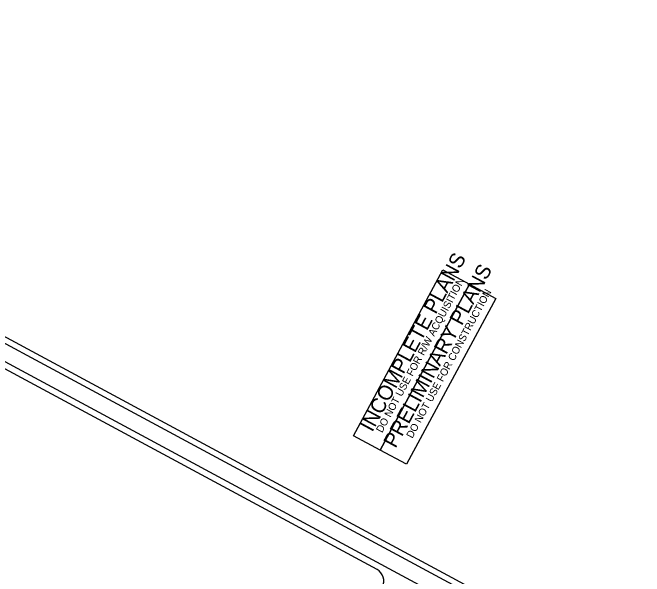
# Model space of a CAD drawing. Extents: x 1376167 to 1379209, y 761324 to 763997.
# Drawn here: x 1377441.6 to 1377934.3, y 763557.6 to 763997.5 of the extents above; entities that cross this region are included whole.
import ezdxf

# ---------------------------------------------------------------- set-up
doc = ezdxf.new("R2010")
doc.units = 0
for name, color, linetype in [('Sheet Plot Border Inside CELL', 7, 'Continuous'), ('Sheet Plot Border Outside CELL', 7, 'Continuous'), ('Sheet Sticker Incomplete CELL', 7, 'Continuous'), ('Sheet Sticker Preliminary CELL', 7, 'Continuous'), ('Sheet Title CELL', 7, 'Continuous')]:
    doc.layers.add(name, color=color, linetype=linetype)

msp = doc.modelspace()

# ---------------------------------------------------------------- linework, layer by layer
at = {"layer": 'Sheet Plot Border Inside CELL'}
msp.add_lwpolyline([(1377121.6, 762015.28), (1377912.43, 763482.18), (1376983.7, 763982.88), (1376192.87, 762515.97)], close=True, dxfattribs=at)
at = {"layer": 'Sheet Plot Border Outside CELL'}
msp.add_lwpolyline([(1376966.07, 763997.49), (1376166.94, 762515.18), (1377135.18, 761993.19), (1377934.31, 763475.5)], close=True, dxfattribs=at)
at = {"layer": 'Sheet Sticker Incomplete CELL'}
msp.add_lwpolyline([(1377728.13, 763656.18), (1377707.44, 763667.33), (1377777.2, 763796.73), (1377797.89, 763785.58)], close=True, dxfattribs=at)
at = {"layer": 'Sheet Sticker Preliminary CELL'}
msp.add_lwpolyline([(1377748.82, 763645.03), (1377728.13, 763656.18), (1377797.89, 763785.58), (1377818.57, 763774.42)], close=True, dxfattribs=at)
at = {"layer": 'Sheet Title CELL'}
for points in [[(1377895.44, 763477.14), (1376988.81, 763965.92)], [(1377725.83, 763562.9), (1376990.83, 763959.15)]]:
    msp.add_lwpolyline(points, dxfattribs=at)
msp.add_arc((1377721.04, 763554.13), 10, 331.6702, 61.6702, dxfattribs=at)

# ---------------------------------------------------------------- texts
at = {"layer": 'Sheet Sticker Incomplete CELL'}
for s, height, p in [('INCOMPLETE PLANS', 11.52, (1377722.08, 763669.61)), ('DO NOT USE FOR R/W ACQUISITION', 5.76, (1377729.74, 763669.17))]:
    msp.add_text(s, height=height, rotation=61.6702, dxfattribs=at).set_placement(p)
at = {"layer": 'Sheet Sticker Preliminary CELL'}
for s, height, p in [('PRELIMINARY PLANS', 11.52, (1377740.32, 763656.99)), ('DO NOT USE FOR CONSTRUCTION', 5.76, (1377753.32, 763664.87))]:
    msp.add_text(s, height=height, rotation=61.6702, dxfattribs=at).set_placement(p)

doc.saveas('drawing.dxf')
